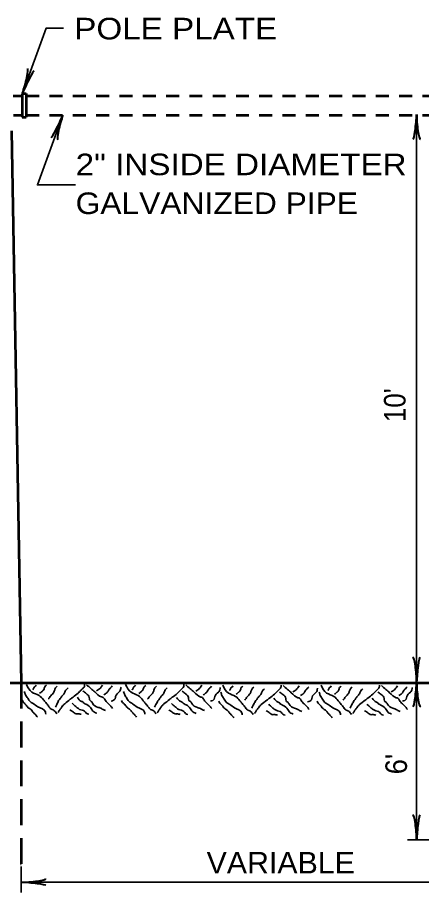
# Model space of a CAD drawing. Extents: x 12366 to 13046, y 9129 to 9570.
# Drawn here: x 12746.6 to 12793.4, y 9373.5 to 9474.9 of the extents above; entities that cross this region are included whole.
import ezdxf
from ezdxf.enums import TextEntityAlignment as Align

# ---------------------------------------------------------------- set-up
doc = ezdxf.new("R2010")
doc.units = 0
doc.linetypes.add('MEDIUM_DASHED', pattern=[4.5, 3, -1.5])
doc.linetypes.add('SHORT_DASHED', pattern=[2.7, 1.5, -1.2])
doc.layers.add('1', color=7, linetype='Continuous', lineweight=53)

msp = doc.modelspace()

# ---------------------------------------------------------------- linework, layer by layer
at = {"layer": '1'}
for p, q in [((12746.065, 9465.812), (12747.104, 9465.812)), ((12747.104, 9466.062), (12747.104, 9463.313)), ((12747.104, 9466.062), (12747.604, 9466.062)), ((12747.604, 9466.062), (12747.604, 9463.313)), ((12746.104, 9463.563), (12747.104, 9463.563)), ((12747.104, 9463.313), (12747.604, 9463.313)), ((12745.886, 9461.744), (12747.002, 9397.801)), ((12722.941, 9397.801), (12909.771, 9397.801))]:
    msp.add_line(p, q, dxfattribs=at)
at = {"layer": '1', "linetype": 'SHORT_DASHED'}
for p, q in [((12747.583, 9465.812), (12808.241, 9465.812)), ((12747.584, 9463.563), (12808.241, 9463.563))]:
    msp.add_line(p, q, dxfattribs=at)
at = {"layer": '1', "linetype": 'MEDIUM_DASHED'}
for p in [(12747.002, 9397.801), (12737.941, 9376.801)]:
    msp.add_line(p, (12747.002, 9376.801), dxfattribs=at)
at = {"layer": '1', "lineweight": 35}
for p, q in [((12810.907, 9379.6), (12791.754, 9379.6)), ((12747.003, 9376.495), (12747.003, 9373.495)), ((12747.004, 9374.68), (12810.943, 9374.68))]:
    msp.add_line(p, q, dxfattribs=at)
for points in [[(12747.162, 9466.11), (12749.898, 9473.627), (12751.898, 9473.627)], [(12751.834, 9463.563), (12748.893, 9455.483), (12753.315, 9455.483)], [(12792.798, 9463.648), (12792.798, 9397.886), (12792.798, 9379.6)]]:
    msp.add_lwpolyline(points, dxfattribs=at)
at = {"layer": '1', "lineweight": 40}
for centre, major_axis, ratio, start_param, end_param in [((12747.276, 9467.23), (-0.464, -1.731), 0.122415, 0.8963533, 3.1415927), ((12747.744, 9467.09), (0.766, 1.59), 0.07063, 6.2823074, 8.5597026), ((12751.252, 9462.583), (0.766, 1.59), 0.07063, 3.1407148, 5.41811), ((12751.72, 9462.443), (0.464, 1.731), 0.122415, 0.8963533, 3.1415927), ((12792.586, 9462.527), (-0.176, -1.756), 0.07063, 6.2823074, 8.5597026), ((12793.074, 9462.557), (-0.156, 1.786), 0.122415, 0.8963533, 3.1415927), ((12792.522, 9398.977), (0.156, -1.786), 0.122415, 0.8963533, 3.1415927), ((12793.01, 9399.006), (0.176, 1.756), 0.07063, 6.2823074, 8.5597026), ((12792.586, 9396.765), (-0.176, -1.756), 0.07063, 6.2823074, 8.5597026), ((12792.586, 9396.765), (-0.176, -1.756), 0.07063, 6.2823074, 8.5597026), ((12793.074, 9396.794), (-0.156, 1.786), 0.122415, 0.8963533, 3.1415927), ((12793.074, 9396.794), (-0.156, 1.786), 0.122415, 0.8963533, 3.1415927), ((12792.522, 9380.691), (0.156, -1.786), 0.122415, 0.8963533, 3.1415927), ((12793.01, 9380.721), (0.176, 1.756), 0.07063, 6.2823074, 8.5597026), ((12748.095, 9374.956), (-1.786, -0.156), 0.122415, 0.8963533, 3.1415927), ((12748.124, 9374.468), (1.756, -0.176), 0.07063, 6.2823074, 8.5597026)]:
    msp.add_ellipse(centre, major_axis=major_axis, ratio=ratio, start_param=start_param, end_param=end_param, dxfattribs=at)
at = {"layer": '1', "lineweight": 35}
for points in [[(12747.606, 9397.604), (12748.245, 9396.708), (12749.077, 9396.324), (12749.589, 9395.812), (12749.845, 9395.493), (12750.165, 9395.109), (12750.421, 9394.789), (12750.805, 9394.597), (12751.124, 9394.213)], [(12748.757, 9397.532), (12748.661, 9397.404), (12748.629, 9397.404), (12748.565, 9397.34), (12748.405, 9397.052), (12748.373, 9396.988)], [(12749.941, 9397.5), (12749.749, 9397.34), (12749.685, 9397.18), (12749.621, 9396.988), (12749.493, 9396.86), (12749.429, 9396.796), (12749.141, 9396.573)], [(12751.188, 9397.404), (12750.996, 9397.212), (12750.868, 9396.892), (12750.709, 9396.573), (12750.357, 9396.189), (12750.229, 9395.997), (12750.165, 9395.901)], [(12754.355, 9397.604), (12754.355, 9397.476), (12754.291, 9397.284), (12754.163, 9397.156), (12754.035, 9397.028), (12753.779, 9396.772), (12753.588, 9396.58), (12753.012, 9396.132), (12752.692, 9395.877), (12752.052, 9395.365), (12751.796, 9395.109), (12751.668, 9394.917), (12751.476, 9394.661), (12751.284, 9394.341)], [(12754.579, 9397.572), (12755.091, 9397.124), (12755.539, 9396.74), (12756.307, 9396.164), (12756.499, 9396.1), (12756.691, 9395.844), (12757.01, 9395.461), (12757.394, 9395.077), (12757.586, 9394.821)], [(12755.731, 9396.86), (12756.179, 9397.18), (12756.275, 9397.308), (12756.435, 9397.532)], [(12756.595, 9396.413), (12756.947, 9396.668), (12757.17, 9396.988), (12757.234, 9397.084), (12757.362, 9397.212), (12757.554, 9397.436)], [(12759.094, 9397.583), (12759.734, 9396.688), (12760.566, 9396.304), (12761.078, 9395.792), (12761.334, 9395.472), (12761.654, 9395.088), (12761.909, 9394.768), (12762.293, 9394.576), (12762.613, 9394.192)], [(12760.246, 9397.512), (12760.15, 9397.384), (12760.118, 9397.384), (12760.054, 9397.32), (12759.894, 9397.032), (12759.862, 9396.968)], [(12761.43, 9397.48), (12761.238, 9397.32), (12761.174, 9397.16), (12761.11, 9396.968), (12760.982, 9396.84), (12760.918, 9396.776), (12760.63, 9396.552)], [(12762.677, 9397.384), (12762.485, 9397.192), (12762.357, 9396.872), (12762.197, 9396.552), (12761.845, 9396.168), (12761.717, 9395.976), (12761.653, 9395.88)], [(12765.844, 9397.583), (12765.844, 9397.455), (12765.78, 9397.263), (12765.652, 9397.136), (12765.524, 9397.007), (12765.268, 9396.752), (12765.076, 9396.56), (12764.5, 9396.112), (12764.181, 9395.856), (12763.541, 9395.344), (12763.285, 9395.088), (12763.157, 9394.896), (12762.965, 9394.64), (12762.773, 9394.32)], [(12766.068, 9397.551), (12766.58, 9397.103), (12767.028, 9396.72), (12767.795, 9396.144), (12767.987, 9396.08), (12768.179, 9395.824), (12768.499, 9395.44), (12768.883, 9395.056), (12769.075, 9394.8)], [(12767.22, 9396.84), (12767.667, 9397.16), (12767.763, 9397.288), (12767.923, 9397.512)], [(12768.083, 9396.392), (12768.435, 9396.648), (12768.659, 9396.968), (12768.723, 9397.064), (12768.851, 9397.192), (12769.043, 9397.416)], [(12770.356, 9397.501), (12770.996, 9396.605), (12771.828, 9396.221), (12772.339, 9395.709), (12772.595, 9395.389), (12772.915, 9395.006), (12773.171, 9394.686), (12773.555, 9394.494), (12773.875, 9394.11)], [(12771.508, 9397.429), (12771.412, 9397.301), (12771.38, 9397.301), (12771.316, 9397.237), (12771.156, 9396.949), (12771.124, 9396.885)], [(12772.691, 9397.397), (12772.499, 9397.237), (12772.435, 9397.077), (12772.371, 9396.885), (12772.243, 9396.757), (12772.179, 9396.693), (12771.891, 9396.469)], [(12777.106, 9397.501), (12777.106, 9397.373), (12777.042, 9397.181), (12776.914, 9397.053), (12776.786, 9396.925), (12776.53, 9396.669), (12776.338, 9396.477), (12775.762, 9396.029), (12775.442, 9395.773), (12774.802, 9395.262), (12774.547, 9395.006), (12774.419, 9394.814), (12774.227, 9394.558), (12774.035, 9394.238)], [(12777.33, 9397.469), (12777.842, 9397.021), (12778.289, 9396.637), (12779.057, 9396.061), (12779.249, 9395.997), (12779.441, 9395.741), (12779.761, 9395.358), (12780.145, 9394.974), (12780.337, 9394.718)], [(12778.481, 9396.757), (12778.929, 9397.077), (12779.025, 9397.205), (12779.185, 9397.429)], [(12779.345, 9396.309), (12779.697, 9396.565), (12779.921, 9396.885), (12779.985, 9396.981), (12780.113, 9397.109), (12780.305, 9397.333)], [(12781.742, 9397.501), (12782.381, 9396.605), (12783.213, 9396.221), (12783.725, 9395.709), (12783.981, 9395.389), (12784.301, 9395.006), (12784.557, 9394.686), (12784.941, 9394.494), (12785.261, 9394.11)], [(12782.893, 9397.429), (12782.797, 9397.301), (12782.765, 9397.301), (12782.701, 9397.237), (12782.541, 9396.949), (12782.509, 9396.885)], [(12784.077, 9397.397), (12783.885, 9397.237), (12783.821, 9397.077), (12783.757, 9396.885), (12783.629, 9396.757), (12783.565, 9396.693), (12783.277, 9396.469)], [(12788.491, 9397.501), (12788.491, 9397.373), (12788.427, 9397.181), (12788.299, 9397.053), (12788.171, 9396.925), (12787.915, 9396.669), (12787.724, 9396.477), (12787.148, 9396.029), (12786.828, 9395.773), (12786.188, 9395.262), (12785.932, 9395.006), (12785.804, 9394.814), (12785.612, 9394.558), (12785.42, 9394.238)], [(12788.715, 9397.469), (12789.227, 9397.021), (12789.675, 9396.637), (12790.443, 9396.061), (12790.635, 9395.997), (12790.827, 9395.741), (12791.146, 9395.358), (12791.53, 9394.974), (12791.722, 9394.718)], [(12789.867, 9396.757), (12790.315, 9397.077), (12790.411, 9397.205), (12790.571, 9397.429)], [(12790.731, 9396.309), (12791.083, 9396.565), (12791.306, 9396.885), (12791.37, 9396.981), (12791.498, 9397.109), (12791.69, 9397.333)], [(12747.382, 9396.797), (12747.51, 9396.413), (12747.766, 9395.997), (12748.085, 9395.581), (12748.405, 9395.389), (12748.949, 9395.005), (12749.813, 9394.429), (12749.845, 9394.173)], [(12752.436, 9397.212), (12752.148, 9396.892), (12751.988, 9396.54), (12751.732, 9396.253), (12751.54, 9395.965), (12751.348, 9395.741), (12751.252, 9395.517), (12751.124, 9395.293), (12750.965, 9394.973)], [(12754.163, 9396.828), (12754.355, 9396.7), (12754.547, 9396.541), (12754.899, 9396.093), (12754.931, 9395.805), (12755.187, 9395.581), (12755.283, 9395.421), (12755.923, 9394.941), (12756.307, 9394.813), (12756.403, 9394.749), (12756.754, 9394.589)], [(12757.426, 9395.677), (12757.874, 9395.933), (12757.938, 9396.221), (12758.354, 9396.733), (12758.482, 9396.892), (12758.546, 9397.148), (12758.578, 9397.276)], [(12758.87, 9396.776), (12758.998, 9396.392), (12759.254, 9395.976), (12759.574, 9395.56), (12759.894, 9395.368), (12760.438, 9394.985), (12761.302, 9394.409), (12761.334, 9394.153)], [(12763.925, 9397.192), (12763.637, 9396.872), (12763.477, 9396.52), (12763.221, 9396.232), (12763.029, 9395.944), (12762.837, 9395.72), (12762.741, 9395.496), (12762.613, 9395.272), (12762.453, 9394.952)], [(12765.652, 9396.808), (12765.844, 9396.68), (12766.036, 9396.52), (12766.388, 9396.072), (12766.42, 9395.784), (12766.676, 9395.56), (12766.772, 9395.4), (12767.412, 9394.921), (12767.795, 9394.793), (12767.891, 9394.729), (12768.243, 9394.569)], [(12768.915, 9395.656), (12769.363, 9395.912), (12769.427, 9396.2), (12769.843, 9396.712), (12769.971, 9396.872), (12770.035, 9397.128), (12770.067, 9397.256)], [(12770.132, 9396.693), (12770.26, 9396.309), (12770.516, 9395.894), (12770.836, 9395.478), (12771.156, 9395.286), (12771.7, 9394.902), (12772.563, 9394.326), (12772.595, 9394.07)], [(12773.939, 9397.301), (12773.747, 9397.109), (12773.619, 9396.789), (12773.459, 9396.469), (12773.107, 9396.086), (12772.979, 9395.894), (12772.915, 9395.798)], [(12775.186, 9397.109), (12774.898, 9396.789), (12774.739, 9396.437), (12774.483, 9396.149), (12774.291, 9395.862), (12774.099, 9395.638), (12774.003, 9395.414), (12773.875, 9395.19), (12773.715, 9394.87)], [(12776.914, 9396.725), (12777.106, 9396.597), (12777.298, 9396.438), (12777.65, 9395.99), (12777.682, 9395.702), (12777.938, 9395.478), (12778.033, 9395.318), (12778.673, 9394.838), (12779.057, 9394.71), (12779.153, 9394.646), (12779.505, 9394.486)], [(12780.177, 9395.574), (12780.625, 9395.83), (12780.689, 9396.118), (12781.104, 9396.629), (12781.232, 9396.789), (12781.296, 9397.045), (12781.328, 9397.173)], [(12781.518, 9396.693), (12781.646, 9396.309), (12781.902, 9395.894), (12782.221, 9395.478), (12782.541, 9395.286), (12783.085, 9394.902), (12783.949, 9394.326), (12783.981, 9394.07)], [(12785.324, 9397.301), (12785.132, 9397.109), (12785.004, 9396.789), (12784.845, 9396.469), (12784.493, 9396.086), (12784.365, 9395.894), (12784.301, 9395.798)], [(12786.572, 9397.109), (12786.284, 9396.789), (12786.124, 9396.437), (12785.868, 9396.149), (12785.676, 9395.862), (12785.484, 9395.638), (12785.388, 9395.414), (12785.26, 9395.19), (12785.101, 9394.87)], [(12788.299, 9396.725), (12788.491, 9396.597), (12788.683, 9396.438), (12789.035, 9395.99), (12789.067, 9395.702), (12789.323, 9395.478), (12789.419, 9395.318), (12790.059, 9394.838), (12790.443, 9394.71), (12790.539, 9394.646), (12790.89, 9394.486)], [(12791.15, 9395.656), (12791.598, 9395.912), (12791.662, 9396.2), (12792.077, 9396.712), (12792.205, 9396.872), (12792.269, 9397.128), (12792.301, 9397.256)], [(12747.126, 9395.773), (12747.254, 9395.549), (12747.51, 9395.293), (12747.83, 9394.909), (12748.118, 9394.717), (12748.373, 9394.397), (12748.629, 9394.141), (12748.885, 9393.822)], [(12752.916, 9395.421), (12753.332, 9395.037), (12753.492, 9394.909), (12753.779, 9394.717), (12754.355, 9394.493), (12754.547, 9394.269), (12754.835, 9394.141)], [(12753.524, 9396.125), (12754.003, 9395.645), (12754.099, 9395.613), (12754.195, 9395.517), (12754.611, 9395.261), (12755.123, 9394.813), (12755.283, 9394.557), (12755.763, 9394.269)], [(12758.614, 9395.752), (12758.742, 9395.528), (12758.998, 9395.272), (12759.318, 9394.888), (12759.606, 9394.697), (12759.862, 9394.377), (12760.118, 9394.121), (12760.374, 9393.801)], [(12764.404, 9395.4), (12764.82, 9395.016), (12764.98, 9394.888), (12765.268, 9394.697), (12765.844, 9394.473), (12766.036, 9394.249), (12766.324, 9394.121)], [(12765.012, 9396.104), (12765.492, 9395.624), (12765.588, 9395.592), (12765.684, 9395.496), (12766.1, 9395.24), (12766.612, 9394.793), (12766.772, 9394.537), (12767.252, 9394.249)], [(12769.876, 9395.67), (12770.004, 9395.446), (12770.26, 9395.19), (12770.58, 9394.806), (12770.868, 9394.614), (12771.124, 9394.294), (12771.38, 9394.038), (12771.636, 9393.718)], [(12775.666, 9395.318), (12776.082, 9394.934), (12776.242, 9394.806), (12776.53, 9394.614), (12777.106, 9394.39), (12777.298, 9394.166), (12777.586, 9394.038)], [(12776.274, 9396.022), (12776.754, 9395.542), (12776.85, 9395.51), (12776.946, 9395.414), (12777.362, 9395.158), (12777.873, 9394.71), (12778.033, 9394.454), (12778.513, 9394.166)], [(12781.262, 9395.67), (12781.39, 9395.446), (12781.646, 9395.19), (12781.966, 9394.806), (12782.253, 9394.614), (12782.509, 9394.294), (12782.765, 9394.038), (12783.021, 9393.718)], [(12787.052, 9395.318), (12787.468, 9394.934), (12787.628, 9394.806), (12787.915, 9394.614), (12788.491, 9394.39), (12788.683, 9394.166), (12788.971, 9394.038)], [(12787.66, 9396.022), (12788.139, 9395.542), (12788.235, 9395.51), (12788.331, 9395.414), (12788.747, 9395.158), (12789.259, 9394.71), (12789.419, 9394.454), (12789.899, 9394.166)], [(12752.628, 9394.653), (12752.852, 9394.525), (12753.268, 9394.237), (12753.332, 9394.205), (12753.524, 9394.205), (12753.94, 9394.141)], [(12764.117, 9394.633), (12764.341, 9394.505), (12764.756, 9394.217), (12764.82, 9394.185), (12765.012, 9394.185), (12765.428, 9394.121)], [(12775.378, 9394.55), (12775.602, 9394.422), (12776.018, 9394.134), (12776.082, 9394.102), (12776.274, 9394.102), (12776.69, 9394.038)], [(12786.764, 9394.55), (12786.988, 9394.422), (12787.404, 9394.134), (12787.468, 9394.102), (12787.66, 9394.102), (12788.075, 9394.038)]]:
    msp.add_spline(points, degree=3, dxfattribs=at)

# ---------------------------------------------------------------- texts
at = {"layer": '1'}
for s, width, p in [('POLE PLATE', 1.15, (12753.15, 9472.342)), ('2" INSIDE DIAMETER', 1.15, (12753.315, 9456.606)), ('GALVANIZED PIPE', 1.1, (12753.315, 9452.106))]:
    msp.add_text(s, height=2.5, dxfattribs=dict(at, width=width)).set_placement(p)
for s, width, p in [("10'", 0.9, (12791.515, 9429.956)), ("6'", 0.95, (12791.68, 9388.374))]:
    msp.add_text(s, height=2.5, rotation=90, dxfattribs=dict(at, width=width)).set_placement(p, align=Align.CENTER)
at = {"layer": '1', "width": 1.05}
msp.add_text('VARIABLE', height=2.5, dxfattribs=at).set_placement((12777.064, 9375.697), align=Align.CENTER)

doc.saveas('drawing.dxf')
